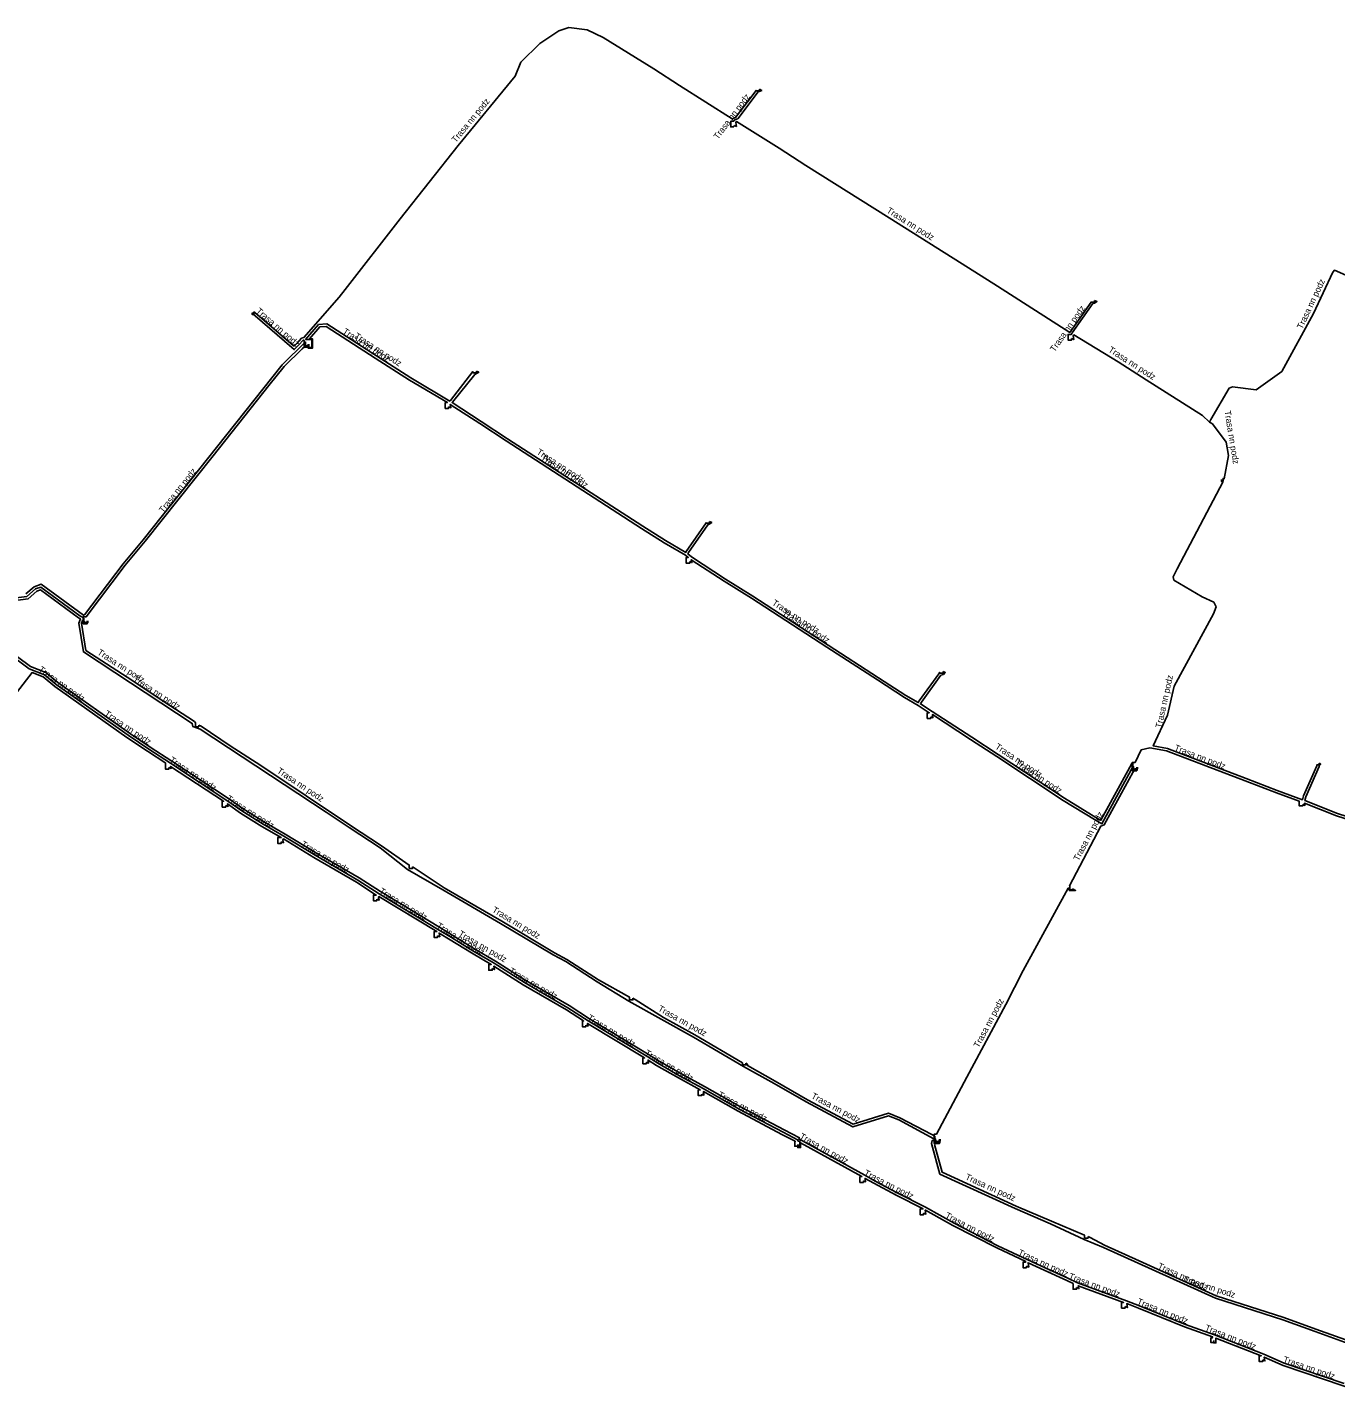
# Model space of a CAD drawing. Extents: x -742082 to -717476, y -1040737 to -1024597.
# Drawn here: x -736211.5 to -736004.4, y -1032916 to -1032698.7 of the extents above; entities that cross this region are included whole.
import ezdxf

# ---------------------------------------------------------------- set-up
doc = ezdxf.new("R2010")
doc.units = 0
doc.layers.add('Level 15', color=7, linetype='Continuous')
doc.layers.add('Level 20', color=7, linetype='Continuous')

msp = doc.modelspace()

# ---------------------------------------------------------------- linework, layer by layer
at = {"layer": 'Level 15'}
for points in [[(-736095.6, -1032708.47), (-736095.6, -1032708.73), (-736096.16, -1032708.73), (-736096.16, -1032708.62), (-736096.16, -1032708.64), (-736099.39, -1032712.94), (-736099.93, -1032713.16), (-736108.28, -1032707.88), (-736112.34, -1032705.24), (-736120.35, -1032700.28), (-736122.92, -1032699.03), (-736125.79, -1032698.68), (-736127.37, -1032699.2), (-736130.37, -1032701.21), (-736133.4, -1032704.16), (-736134.27, -1032706.37), (-736143.33, -1032717.34), (-736152.52, -1032728.97), (-736161.21, -1032740.15), (-736162.16, -1032741.36), (-736167.74, -1032747.73), (-736168.11, -1032747.85), (-736168.88, -1032748.71), (-736169.29, -1032749.11), (-736169.42, -1032749.01), (-736175.18, -1032744.03), (-736175.65, -1032743.67), (-736175.56, -1032744.02), (-736175.91, -1032743.86)], [(-736099.61, -1032714.17), (-736099.61, -1032714.29), (-736099.71, -1032714.43), (-736100.16, -1032714.43), (-736100.16, -1032713.52), (-736099.7, -1032713.52), (-736099.62, -1032713.37), (-736099.27, -1032713.21), (-736099.05, -1032713.15), (-736095.83, -1032708.86), (-736095.65, -1032708.83), (-736095.25, -1032708.63), (-736095.6, -1032708.47)], [(-736042.57, -1032741.89), (-736042.57, -1032742.15), (-736043.12, -1032742.15), (-736046.49, -1032746.94), (-736057.95, -1032739.63), (-736062.51, -1032736.72), (-736075.1, -1032728.79), (-736088.27, -1032720.54), (-736092.49, -1032717.79), (-736099.27, -1032713.57), (-736099.36, -1032713.73), (-736099.26, -1032714.33), (-736099.61, -1032714.17)], [(-735988.55, -1032729.46), (-735988.46, -1032729.96), (-735988.45, -1032730.43), (-735991.98, -1032737.38), (-735992.23, -1032737.87), (-735992.52, -1032738.35), (-735993.9, -1032741.15), (-735994.44, -1032741.59), (-736004.59, -1032737.11), (-736004.87, -1032737.43), (-736007.93, -1032743.94), (-736012.91, -1032753.1), (-736016.99, -1032756.02), (-736020.75, -1032755.53), (-736021.28, -1032755.77), (-736024.14, -1032760.7), (-736024.37, -1032761.13)], [(-736046.21, -1032747.9), (-736046.21, -1032748.16), (-736046.76, -1032748.16), (-736046.76, -1032747.25), (-736046.27, -1032747.25), (-736046.19, -1032747.13), (-736046.13, -1032747.03), (-736042.83, -1032742.34), (-736042.59, -1032742.3), (-736042.21, -1032742.05), (-736042.57, -1032741.89)], [(-736166.99, -1032748.78), (-736166.99, -1032749.25), (-736167.69, -1032749.25), (-736167.69, -1032748.23), (-736167.82, -1032748.12), (-736168.59, -1032748.98), (-736169.27, -1032749.65), (-736169.65, -1032749.33), (-736175.43, -1032744.34), (-736175.73, -1032744.12), (-736175.91, -1032744.12), (-736175.91, -1032743.86)], [(-736140.43, -1032753.07), (-736140.43, -1032753.33), (-736140.97, -1032753.33), (-736140.97, -1032753.13), (-736144.51, -1032757.7), (-736144.66, -1032757.81), (-736150.8, -1032754.15), (-736156.24, -1032750.67), (-736164.09, -1032745.6), (-736165.42, -1032745.7), (-736167.48, -1032748.04), (-736166.48, -1032748.04), (-736166.48, -1032749.35), (-736167.02, -1032749.35), (-736167.02, -1032748.78)], [(-736144.82, -1032758.7), (-736144.82, -1032758.96), (-736145.37, -1032758.96), (-736145.37, -1032758.05), (-736145.03, -1032758.05), (-736151.01, -1032754.49), (-736156.46, -1032751), (-736164.2, -1032746.01), (-736165.23, -1032746.08), (-736166.86, -1032747.94), (-736166.38, -1032747.94), (-736166.38, -1032749.45), (-736167.04, -1032749.45), (-736167.04, -1032748.78)], [(-736166.94, -1032748.78), (-736166.94, -1032749.05), (-736167.49, -1032749.05), (-736167.49, -1032748.45), (-736171.18, -1032752.08), (-736193.18, -1032779.74), (-736196.34, -1032783.54), (-736202.48, -1032791.62), (-736202.63, -1032791.7), (-736209.32, -1032786.8), (-736210.43, -1032787.18), (-736211.75, -1032788.33)], [(-736202.02, -1032792.58), (-736202.02, -1032793.05), (-736202.67, -1032793.05), (-736202.67, -1032791.94), (-736202.2, -1032791.94), (-736202.21, -1032791.93), (-736196.03, -1032783.79), (-736192.87, -1032779.99), (-736182.1, -1032766.49), (-736173.3, -1032755.35), (-736170.88, -1032752.35), (-736168.01, -1032749.54), (-736167.59, -1032749.15), (-736166.97, -1032749.15), (-736166.97, -1032748.78)], [(-736024.37, -1032761.13), (-736025.5, -1032760.07), (-736034.38, -1032754.42), (-736038.82, -1032751.58), (-736045.85, -1032747.34), (-736045.96, -1032747.5), (-736045.86, -1032748.06), (-736046.21, -1032747.9)], [(-736103.53, -1032776.85), (-736103.53, -1032777.11), (-736104.08, -1032777.11), (-736104.08, -1032777.07), (-736107.21, -1032781.59), (-736107.29, -1032781.75), (-736110.49, -1032779.89), (-736114.08, -1032777.61), (-736135.48, -1032763.79), (-736139.67, -1032761.03), (-736144.29, -1032758.04), (-736144.23, -1032758), (-736140.66, -1032753.59), (-736140.07, -1032753.23), (-736140.43, -1032753.07)], [(-736106.66, -1032783.2), (-736106.66, -1032783.46), (-736107.21, -1032783.46), (-736107.21, -1032782.55), (-736106.89, -1032782.55), (-736107.32, -1032782.19), (-736110.7, -1032780.23), (-736114.3, -1032777.95), (-736135.7, -1032764.12), (-736139.89, -1032761.36), (-736144.57, -1032758.34), (-736144.47, -1032758.86), (-736144.82, -1032758.7)], [(-736022.4, -1032770.19), (-736022.4, -1032770.45), (-736022.22, -1032770.45), (-736022.22, -1032770.04), (-736022.06, -1032770.12), (-736021.38, -1032766.42), (-736021.72, -1032764.32), (-736023.92, -1032761.43), (-736024.37, -1032761.13)], [(-736022.47, -1032770.19), (-736022.47, -1032770.55), (-736022.22, -1032770.55), (-736029.5, -1032784.33), (-736030.11, -1032785.6), (-736030.01, -1032786.14), (-736025.54, -1032788.76), (-736023.7, -1032789.63), (-736023.31, -1032790.34), (-736023.74, -1032791.47), (-736029.98, -1032802.9), (-736031, -1032807.5), (-736033.28, -1032812.37), (-736031.05, -1032812.77), (-736018.59, -1032817.53), (-736013.64, -1032819.42), (-736009.66, -1032820.89), (-736009.5, -1032820.28), (-736007.41, -1032815.51), (-736007.39, -1032815.38), (-736007.02, -1032815.38), (-736007.02, -1032815.12)], [(-736066.55, -1032800.62), (-736066.55, -1032800.88), (-736067.1, -1032800.88), (-736067.1, -1032800.75), (-736067.23, -1032800.95), (-736070.33, -1032805.22), (-736070.47, -1032805.52), (-736072.47, -1032804.38), (-736076.75, -1032801.61), (-736084.73, -1032796.42), (-736096.68, -1032788.66), (-736101.01, -1032785.98), (-736106.37, -1032782.46), (-736106.95, -1032781.98), (-736106.86, -1032781.79), (-736103.81, -1032777.39), (-736103.45, -1032777.23), (-736103.18, -1032777.01), (-736103.53, -1032776.85)], [(-736201.99, -1032792.58), (-736201.99, -1032792.95), (-736202.57, -1032792.95), (-736202.57, -1032792.17), (-736202.79, -1032792.01), (-736203.22, -1032791.77), (-736209.38, -1032787.24), (-736210.23, -1032787.53), (-736211.58, -1032788.71), (-736214.5, -1032789.09), (-736221.54, -1032784.3), (-736226.12, -1032781.29), (-736229.7, -1032778.75), (-736229.71, -1032778.27), (-736230.06, -1032778.11)], [(-736068.51, -1032807.77), (-736068.51, -1032808.03), (-736069.06, -1032808.03), (-736069.06, -1032807.12), (-736068.73, -1032807.12), (-736070.49, -1032805.97), (-736072.68, -1032804.72), (-736076.96, -1032801.94), (-736084.95, -1032796.76), (-736096.89, -1032789), (-736101.22, -1032786.32), (-736106.41, -1032782.92), (-736106.31, -1032783.36), (-736106.66, -1032783.2)], [(-736067.07, -1032874.63), (-736067.07, -1032875.1), (-736067.76, -1032875.1), (-736067.76, -1032874.55), (-736068.01, -1032874.53), (-736073.58, -1032871.57), (-736075.21, -1032870.91), (-736080.83, -1032872.66), (-736088.23, -1032868.71), (-736093.31, -1032865.78), (-736098.16, -1032863.09), (-736106.06, -1032858.44), (-736116.31, -1032852.77), (-736121.3, -1032849.73), (-736126.29, -1032846.5), (-736128.27, -1032845.46), (-736136.62, -1032840.47), (-736145.74, -1032835.16), (-736151.31, -1032831.95), (-736155.66, -1032828.53), (-736160.56, -1032825.3), (-736164.2, -1032822.87), (-736184.18, -1032809.72), (-736185.31, -1032809.32), (-736185.41, -1032808.81), (-736202.65, -1032797.5), (-736203.36, -1032792.93), (-736203.11, -1032792.29), (-736203.44, -1032792.1), (-736209.45, -1032787.69), (-736210.02, -1032787.89), (-736211.41, -1032789.09), (-736214.59, -1032789.51)], [(-736201.92, -1032792.58), (-736201.92, -1032792.85), (-736202.46, -1032792.85), (-736202.46, -1032792.73), (-736202.77, -1032792.52), (-736202.95, -1032792.97), (-736202.28, -1032797.27), (-736194.84, -1032802.08), (-736190.02, -1032805.3), (-736185.08, -1032808.52), (-736184.92, -1032808.7), (-736184.92, -1032809.34), (-736184.37, -1032809.34), (-736184.37, -1032809.08)], [(-736089.54, -1032875.46), (-736089.54, -1032875.83), (-736089.22, -1032875.83), (-736089.22, -1032874.92), (-736089.53, -1032874.92), (-736089.47, -1032874.75), (-736091.89, -1032873.49), (-736098.82, -1032869.84), (-736104.51, -1032866.61), (-736108.27, -1032864.56), (-736111.71, -1032862.6), (-736113.3, -1032861.59), (-736122.76, -1032855.88), (-736125.94, -1032853.81), (-736132.81, -1032849.84), (-736137.6, -1032846.78), (-736141.02, -1032844.79), (-736144.37, -1032842.72), (-736146.31, -1032841.53), (-736155.83, -1032835.77), (-736159.21, -1032833.6), (-736165.97, -1032829.67), (-736170.9, -1032826.68), (-736174.19, -1032824.77), (-736177.55, -1032822.67), (-736179.76, -1032821.12), (-736188.88, -1032815.12), (-736192.28, -1032812.89), (-736195.56, -1032810.69), (-736206.95, -1032802.66), (-736208.79, -1032801.11), (-736211.22, -1032800.17), (-736217.43, -1032795.56)], [(-736003.08, -1032913.28), (-736012.56, -1032910.07), (-736015.75, -1032908.63), (-736023.57, -1032905.58), (-736028.19, -1032903.92), (-736035.45, -1032900.97), (-736037.5, -1032900.2), (-736045.28, -1032897.33), (-736046.8, -1032896.62), (-736050.41, -1032894.99), (-736053.11, -1032893.71), (-736057.87, -1032891.47), (-736064.81, -1032887.9), (-736069.35, -1032885.37), (-736073.8, -1032883.11), (-736077.3, -1032881.24), (-736078.95, -1032880.33), (-736089.38, -1032874.57), (-736089.29, -1032874.39), (-736091.7, -1032873.14), (-736098.62, -1032869.48), (-736104.32, -1032866.26), (-736108.08, -1032864.21), (-736111.5, -1032862.26), (-736113.08, -1032861.24), (-736122.55, -1032855.54), (-736125.73, -1032853.46), (-736132.6, -1032849.5), (-736137.39, -1032846.44), (-736140.81, -1032844.45), (-736144.16, -1032842.38), (-736146.1, -1032841.19), (-736155.62, -1032835.43), (-736159, -1032833.26), (-736165.76, -1032829.33), (-736170.7, -1032826.34), (-736173.98, -1032824.43), (-736177.33, -1032822.33), (-736179.53, -1032820.79), (-736188.66, -1032814.78), (-736192.05, -1032812.56), (-736195.33, -1032810.36), (-736206.7, -1032802.34), (-736208.58, -1032800.76), (-736211.02, -1032799.82), (-736217.24, -1032795.21)], [(-736189.1, -1032815.77), (-736189.1, -1032816.03), (-736189.65, -1032816.03), (-736189.65, -1032815.12), (-736189.61, -1032815.12), (-736192.5, -1032813.23), (-736195.79, -1032811.02), (-736207.19, -1032802.98), (-736208.99, -1032801.46), (-736210.77, -1032800.77), (-736217.91, -1032809.97), (-736217.78, -1032810.14), (-736218.1, -1032810.14), (-736218.1, -1032810.84), (-736217.65, -1032810.84), (-736217.65, -1032810.68)], [(-736035.84, -1032815.74), (-736035.84, -1032816.2), (-736036.53, -1032816.2), (-736036.53, -1032815.1), (-736036.68, -1032815.14), (-736041.56, -1032824.15), (-736042.39, -1032823.68), (-736047.34, -1032820.65), (-736057.81, -1032813.73), (-736061.98, -1032811), (-736068.3, -1032806.92), (-736070.13, -1032805.73), (-736069.98, -1032805.43), (-736066.9, -1032801.17), (-736066.5, -1032801.09), (-736066.2, -1032800.78), (-736066.55, -1032800.62)], [(-736035.81, -1032815.74), (-736035.81, -1032816.1), (-736036.43, -1032816.1), (-736036.43, -1032815.62), (-736036.47, -1032815.6), (-736041.4, -1032824.7), (-736042.59, -1032824.02), (-736047.55, -1032820.99), (-736058.03, -1032814.07), (-736062.2, -1032811.34), (-736068.25, -1032807.43), (-736068.16, -1032807.93), (-736068.51, -1032807.77)], [(-736150.52, -1032831.49), (-736150.52, -1032831.76), (-736151.07, -1032831.76), (-736151.07, -1032831.23), (-736155.44, -1032828.2), (-736160.34, -1032824.97), (-736174.58, -1032815.5), (-736179.39, -1032812.35), (-736184.02, -1032809.24), (-736184.37, -1032809.08)], [(-736009.61, -1032821.62), (-736009.61, -1032821.88), (-736010.16, -1032821.88), (-736010.16, -1032821.13), (-736013.78, -1032819.79), (-736018.73, -1032817.9), (-736031.16, -1032813.16), (-736033.83, -1032812.68), (-736035.18, -1032812.99), (-736036.17, -1032815), (-736036.63, -1032815), (-736036.63, -1032816.3), (-736035.89, -1032816.3), (-736035.89, -1032815.74)], [(-736180.1, -1032821.79), (-736180.1, -1032822.05), (-736180.65, -1032822.05), (-736180.65, -1032821.14), (-736180.45, -1032821.14), (-736188.84, -1032815.62), (-736188.74, -1032815.93), (-736189.1, -1032815.77)], [(-736035.79, -1032815.74), (-736035.79, -1032816), (-736036.19, -1032816), (-736041.04, -1032824.88), (-736041.59, -1032825.06), (-736046.55, -1032834.51), (-736046.49, -1032834.52), (-736046.49, -1032835.15), (-736046.04, -1032835.15), (-736046.04, -1032834.99)], [(-736007.02, -1032815.12), (-736006.76, -1032815.28), (-736007.01, -1032815.53), (-736007.02, -1032815.62), (-736009.12, -1032820.41), (-736009.29, -1032821.03), (-736004.11, -1032823.08), (-735999.34, -1032824.61), (-735984.95, -1032830.05), (-735975.52, -1032833.54), (-735970.4, -1032835.39), (-735968.95, -1032835.96), (-735968.81, -1032835.73), (-735966.96, -1032830.65), (-735966.55, -1032830.65), (-735966.46, -1032830.5), (-735966.46, -1032830.39)], [(-736171.33, -1032827.54), (-736171.33, -1032827.8), (-736171.88, -1032827.8), (-736171.88, -1032826.89), (-736171.33, -1032826.89), (-736174.4, -1032825.11), (-736177.77, -1032823), (-736179.84, -1032821.55), (-736179.74, -1032821.95), (-736180.1, -1032821.79)], [(-735965.26, -1032838.34), (-735965.26, -1032838.6), (-735965.81, -1032838.6), (-735965.81, -1032837.86), (-735966.03, -1032837.57), (-735968.93, -1032836.39), (-735970.54, -1032835.77), (-735975.65, -1032833.91), (-735985.09, -1032830.42), (-735999.47, -1032824.98), (-736004.25, -1032823.46), (-736009.35, -1032821.44), (-736009.26, -1032821.78), (-736009.61, -1032821.62)], [(-736156.17, -1032836.62), (-736156.17, -1032836.88), (-736156.72, -1032836.88), (-736156.72, -1032835.97), (-736156.27, -1032835.97), (-736159.42, -1032833.94), (-736166.17, -1032830.01), (-736170.98, -1032827.1), (-736171.07, -1032827.22), (-736170.97, -1032827.7), (-736171.33, -1032827.54)], [(-736115.66, -1032852.32), (-736115.66, -1032852.58), (-736116.21, -1032852.58), (-736116.21, -1032852.12), (-736121.1, -1032849.39), (-736126.09, -1032846.16), (-736128.07, -1032845.11), (-736136.42, -1032840.13), (-736140.52, -1032837.74), (-736145.53, -1032834.82), (-736150.27, -1032831.66), (-736150.52, -1032831.49)], [(-736146.58, -1032842.42), (-736146.58, -1032842.68), (-736147.13, -1032842.68), (-736147.13, -1032841.77), (-736146.69, -1032841.77), (-736155.89, -1032836.21), (-736155.92, -1032836.25), (-736155.82, -1032836.78), (-736156.17, -1032836.62)], [(-736046.04, -1032834.99), (-736045.58, -1032835.25), (-736046.59, -1032835.25), (-736046.59, -1032834.91), (-736046.75, -1032834.88), (-736053.85, -1032847.9), (-736056.64, -1032853.31), (-736062.78, -1032864.79), (-736067.61, -1032873.79), (-736067.96, -1032873.79), (-736067.96, -1032875.3), (-736067.12, -1032875.3), (-736067.12, -1032874.63)], [(-736137.93, -1032847.61), (-736137.93, -1032847.87), (-736138.48, -1032847.87), (-736138.48, -1032846.96), (-736138.08, -1032846.96), (-736141.22, -1032845.13), (-736144.58, -1032843.06), (-736146.33, -1032841.99), (-736146.23, -1032842.58), (-736146.58, -1032842.42)], [(-736123.1, -1032856.55), (-736123.1, -1032856.81), (-736123.65, -1032856.81), (-736123.65, -1032855.9), (-736123.47, -1032855.9), (-736126.15, -1032854.15), (-736133.02, -1032850.18), (-736137.66, -1032847.22), (-736137.68, -1032847.24), (-736137.58, -1032847.77), (-736137.93, -1032847.61)], [(-736097.78, -1032862.58), (-736097.77, -1032862.86), (-736098.33, -1032862.84), (-736098.33, -1032862.53), (-736105.86, -1032858.09), (-736110.79, -1032855.36), (-736115.31, -1032852.48), (-736115.66, -1032852.32)], [(-736113.52, -1032862.4), (-736113.52, -1032862.66), (-736114.07, -1032862.66), (-736114.07, -1032861.75), (-736113.8, -1032861.75), (-736122.84, -1032856.3), (-736122.74, -1032856.71), (-736123.1, -1032856.55)], [(-736104.76, -1032867.46), (-736104.76, -1032867.72), (-736105.31, -1032867.72), (-736105.31, -1032866.81), (-736104.99, -1032866.81), (-736108.46, -1032864.91), (-736111.92, -1032862.94), (-736113.26, -1032862.08), (-736113.17, -1032862.56), (-736113.52, -1032862.4)], [(-736067.09, -1032874.63), (-736067.09, -1032875.2), (-736067.86, -1032875.2), (-736067.86, -1032874.14), (-736068.35, -1032873.88), (-736073.41, -1032871.21), (-736075.19, -1032870.49), (-736080.79, -1032872.23), (-736088.03, -1032868.36), (-736093.12, -1032865.43), (-736097.52, -1032862.97), (-736097.52, -1032862.74), (-736097.78, -1032862.58)], [(-736089.51, -1032875.46), (-736089.51, -1032875.73), (-736090.03, -1032875.73), (-736090.03, -1032875.02), (-736089.99, -1032875.02), (-736089.96, -1032874.95), (-736092.07, -1032873.85), (-736099.01, -1032870.19), (-736104.5, -1032867.08), (-736104.4, -1032867.62), (-736104.76, -1032867.46)], [(-736089.56, -1032875.46), (-736089.56, -1032875.93), (-736089.12, -1032875.93), (-736089.12, -1032875.17), (-736079.41, -1032880.53), (-736079.72, -1032880.53), (-736079.72, -1032881.44), (-736079.17, -1032881.44), (-736079.17, -1032881.18)], [(-736067.04, -1032874.63), (-736067.04, -1032875), (-736067.66, -1032875), (-736067.66, -1032874.84), (-736068.28, -1032874.83), (-736068.37, -1032875.28), (-736067.04, -1032880.14), (-736055.14, -1032885.57), (-736049.56, -1032887.98), (-736044.22, -1032890.47), (-736041.18, -1032891.74), (-736035.67, -1032894.21), (-736023.45, -1032899.75), (-736012.76, -1032903.18), (-736007.65, -1032905.02), (-736001.86, -1032907.14), (-735996.09, -1032908.81), (-735991.54, -1032910.3), (-735980.34, -1032913.78), (-735979.63, -1032913.73), (-735979.63, -1032913.86), (-735979.14, -1032913.86), (-735979.14, -1032913.6)], [(-736067.02, -1032874.63), (-736067.02, -1032874.9), (-736067.31, -1032874.9), (-736067.9, -1032875.45), (-736066.7, -1032879.85), (-736054.98, -1032885.2), (-736049.41, -1032887.61), (-736044.16, -1032889.81), (-736044.16, -1032890.26), (-736043.61, -1032890.26), (-736043.61, -1032890)], [(-736079.17, -1032881.18), (-736078.81, -1032881.34), (-736078.91, -1032880.81), (-736077.49, -1032881.59), (-736073.99, -1032883.46), (-736069.71, -1032885.64), (-736069.72, -1032885.65), (-736070.18, -1032885.65), (-736070.18, -1032886.56), (-736069.63, -1032886.56), (-736069.63, -1032886.3)], [(-736069.63, -1032886.3), (-736069.27, -1032886.46), (-736069.37, -1032885.85), (-736069.36, -1032885.82), (-736064.99, -1032888.25), (-736058.05, -1032891.83), (-736053.46, -1032893.99), (-736053.48, -1032894.06), (-736053.9, -1032894.06), (-736053.9, -1032894.96), (-736053.35, -1032894.96), (-736053.35, -1032894.71)], [(-736043.61, -1032890), (-736043.26, -1032890.16), (-736041.01, -1032891.39), (-736035.51, -1032893.85), (-736023.31, -1032899.38), (-736012.63, -1032902.81), (-736007.52, -1032904.65), (-736002.04, -1032906.65), (-736002.04, -1032906.85), (-736001.48, -1032906.85), (-736001.48, -1032906.59)], [(-736053.35, -1032894.71), (-736053, -1032894.86), (-736053.1, -1032894.17), (-736053.1, -1032894.17), (-736050.57, -1032895.35), (-736046.97, -1032896.99), (-736045.96, -1032897.45), (-736045.96, -1032898.35), (-736045.41, -1032898.35), (-736045.41, -1032898.09)], [(-736045.41, -1032898.09), (-736045.06, -1032898.25), (-736045.16, -1032897.8), (-736037.99, -1032900.44), (-736038.29, -1032900.44), (-736038.29, -1032901.35), (-736037.74, -1032901.35), (-736037.74, -1032901.09)], [(-736023.67, -1032906.49), (-736023.67, -1032906.76), (-736024.18, -1032906.76), (-736024.18, -1032906.06), (-736023.94, -1032906.06), (-736023.89, -1032905.89), (-736028.34, -1032904.29), (-736035.6, -1032901.34), (-736037.48, -1032900.63), (-736037.48, -1032900.64), (-736037.38, -1032901.25), (-736037.74, -1032901.09)], [(-736023.7, -1032906.49), (-736023.7, -1032906.86), (-736023.37, -1032906.86), (-736023.37, -1032906.08), (-736016.18, -1032908.89), (-736016.5, -1032908.89), (-736016.5, -1032909.8), (-736015.95, -1032909.8), (-736015.95, -1032909.54)], [(-735999.26, -1032915.71), (-735999.26, -1032915.97), (-735999.81, -1032915.97), (-735999.81, -1032915.06), (-735999.42, -1032915.06), (-735999.38, -1032914.95), (-736003.21, -1032913.66), (-736012.7, -1032910.44), (-736015.7, -1032909.09), (-736015.6, -1032909.7), (-736015.95, -1032909.54)]]:
    msp.add_lwpolyline(points, dxfattribs=at)

# ---------------------------------------------------------------- texts
at = {"layer": 'Level 20'}
for rotation, p in [(50.4615, (-736143.69, -1032716.99)), (53.1001, (-736102.18, -1032716.48)), (327.7999, (-736075.58, -1032727.89)), (64.834, (-736009.69, -1032746.51)), (54.9475, (-736048.9, -1032750.11)), (319.1758, (-736175.4, -1032743.7)), (327.1801, (-736161.7, -1032747.02)), (327.3306, (-736159.84, -1032747.76)), (327.3496, (-736040.48, -1032749.92)), (279.2356, (-736022.01, -1032759.39)), (327.1358, (-736130.99, -1032766.1)), (327.1357, (-736130.32, -1032767.01)), (51.4334, (-736190, -1032775.59)), (327.0012, (-736093.72, -1032789.98)), (327.0016, (-736092.08, -1032791.53)), (327.0764, (-736200.52, -1032797.81)), (324.8285, (-736209.85, -1032800.49)), (326.7449, (-736194.85, -1032802.02)), (77.5465, (-736031.98, -1032809.62)), (326.1251, (-736199.42, -1032807.5)), (326.5443, (-736058.41, -1032812.73)), (339.1146, (-736030.03, -1032813.06)), (326.6606, (-736189.12, -1032814.84)), (326.544, (-736055.27, -1032815.29)), (326.3954, (-736172.09, -1032816.56)), (327.9057, (-736180.1, -1032820.95)), (62.2732, (-736045.1, -1032830.67)), (329.8288, (-736168.3, -1032828.2)), (328.8413, (-736155.91, -1032835.61)), (329.1817, (-736138.03, -1032838.59)), (328.3131, (-736146.83, -1032841.09)), (329.7977, (-736143.37, -1032842.38)), (330.0245, (-736135.37, -1032848.25)), (330.975, (-736111.77, -1032854.24)), (61.9055, (-736060.91, -1032860.23)), (328.9278, (-736122.94, -1032855.66)), (330.3498, (-736113.87, -1032861.25)), (332.1796, (-736102.3, -1032867.88)), (331.9372, (-736087.51, -1032868.07)), (331.1118, (-736089.37, -1032874.46)), (333.0449, (-736079.16, -1032880.27)), (335.4839, (-736063.13, -1032880.93)), (332.736, (-736066.32, -1032887)), (335.6373, (-736054.78, -1032892.9)), (335.6056, (-736032.66, -1032895.03)), (339.7785, (-736046.75, -1032896.68)), (342.2137, (-736028.61, -1032897.15)), (337.8903, (-736035.93, -1032900.66)), (338.6869, (-736025.19, -1032904.84)), (341.2937, (-736012.81, -1032909.88))]:
    msp.add_text('Trasa nn podz', height=1, rotation=rotation, dxfattribs=at).set_placement(p)

doc.saveas('drawing.dxf')
